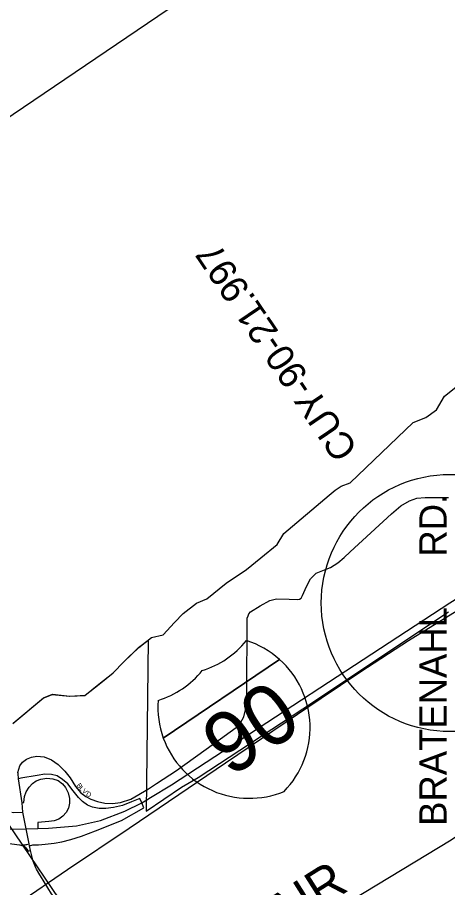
# Model space of a CAD drawing. Extents: x 2139079 to 2262683, y 1235796 to 1334992.
# Drawn here: x 2206334 to 2210756, y 1289914 to 1298857 of the extents above; entities that cross this region are included whole.
import ezdxf

# ---------------------------------------------------------------- set-up
doc = ezdxf.new("R2010")
doc.units = 0
for name, color, linetype in [('Default', 7, 'Continuous'), ('GM_X_City_Street', 7, 'Continuous'), ('GM_X_City_Street_Text', 7, 'Continuous'), ('GM_X_Interchange_Ramps', 7, 'Continuous'), ('GM_X_Interstate_Route', 7, 'Continuous'), ('GM_X_Interstate_Shield', 7, 'Continuous'), ('GM_X_Major_Lake', 7, 'Continuous'), ('GM_X_Rail_Line', 7, 'Continuous'), ('GM_X_US_Route', 7, 'Continuous'), ('SH_Text', 7, 'Continuous')]:
    doc.layers.add(name, color=color, linetype=linetype)

msp = doc.modelspace()

# ---------------------------------------------------------------- linework, layer by layer
at = {"layer": 'GM_X_City_Street'}
for points in [[(2207681, 1290929.7), (2207712.2, 1290948), (2207764.3, 1290982.2), (2207968.5, 1291116.2), (2208359.1, 1291397.6), (2208582.1, 1291558.9), (2208626.3, 1291606.2), (2208661.3, 1291667.1), (2208688.8, 1291783), (2208690.3, 1291929.4), (2208694.1, 1292655.8), (2208696.7, 1292682), (2208704, 1292708), (2208714.1, 1292728.4), (2208729.9, 1292747.6), (2208827.8, 1292810), (2208929, 1292864.9), (2208995.5, 1292881), (2209128.3, 1292879.4), (2209208.4, 1292875.5), (2209233.5, 1292879.4), (2209249.9, 1292886.6), (2209263.4, 1292917), (2209305.9, 1293006.8), (2209345.4, 1293085.9), (2209405.2, 1293145.7), (2209489.7, 1293178.4), (2209552, 1293202.3), (2209628.9, 1293250.3), (2209692.4, 1293305.9), (2209753.9, 1293365.6), (2210179.9, 1293754.7), (2210275.8, 1293835.9), (2210363.2, 1293888.6), (2210439, 1293915), (2210524.9, 1293923.8), (2210765.7, 1293921.8)], [(2206637.8, 1287887.1), (2206870.7, 1288028.3), (2207250.4, 1288258.5), (2210791.9, 1290405.9), (2211061.9, 1290587.5), (2211375.2, 1290789.8), (2211429.3, 1290818.3), (2211504.8, 1290848.2), (2211604.5, 1290868.2), (2211952.5, 1290931.9), (2212611.7, 1291058.6), (2213914.1, 1291343.2), (2214033.3, 1291373.4), (2214154, 1291387), (2214425, 1291386.3)], [(2206340.6, 1291086.3), (2206339.6, 1291096.1), (2206358.4, 1291163.3), (2206386.6, 1291202.2), (2206426.9, 1291233.1), (2206478.4, 1291253.6), (2206534.8, 1291263.5), (2206607.9, 1291256.6), (2206683.3, 1291226.8), (2206752, 1291180.4), (2206822.1, 1291111.8), (2206877.2, 1291041.1), (2206932, 1290953.4), (2206986.9, 1290888.6), (2207035.7, 1290850.5), (2207088.3, 1290822.3), (2207156.8, 1290797.9), (2207233.1, 1290781.1), (2207312.3, 1290779.6), (2207392.3, 1290788), (2207498.9, 1290822.9), (2207681, 1290929.7)], [(2206276.6, 1290687.7), (2206298.3, 1290687), (2206390.7, 1290690), (2206381.6, 1290785.7), (2206346.1, 1291033.1), (2206340.6, 1291086.3)], [(2206455.1, 1290363.6), (2206424.2, 1290518.9), (2206390.7, 1290690)], [(2206524.5, 1290115.7), (2206497.5, 1290183.6), (2206469.8, 1290294.1), (2206459.4, 1290342.2), (2206455.1, 1290363.6)], [(2206572.2, 1290035.5), (2206565.6, 1290046.4), (2206529.4, 1290103.4), (2206524.5, 1290115.7)], [(2206870.7, 1288028.3), (2206801.9, 1288131.6), (2206763, 1288225.5), (2206736.2, 1288313.5), (2206725.6, 1288381.6), (2206736.6, 1288498), (2206777, 1288676.9), (2206816.2, 1288773.5), (2206865, 1288938.8), (2206886.9, 1289050.4), (2206900.2, 1289207.1), (2206899.1, 1289367.4), (2206876.7, 1289479), (2206838.2, 1289622.3), (2206788, 1289727), (2206684.4, 1289851), (2206572.2, 1290035.5)]]:
    msp.add_lwpolyline(points, dxfattribs=at)
at = {"layer": 'GM_X_Interchange_Ramps'}
for points in [[(2207611.2, 1290784.2), (2207591.3, 1290829.6), (2207506.3, 1290794.2), (2207412.4, 1290758.5), (2207323.1, 1290736), (2207241.2, 1290726.5), (2207174, 1290727.1), (2207106.9, 1290739.5), (2207053, 1290761.9), (2207002.2, 1290798.9), (2206960.3, 1290838.8), (2206908.3, 1290908), (2206850.5, 1290981.6), (2206796.9, 1291026), (2206741.7, 1291061.6), (2206683.4, 1291075.3), (2206614.7, 1291078.8), (2206537.2, 1291066.4), (2206370.4, 1291037.3), (2206346.1, 1291033.1)], [(2206381.6, 1290785.7), (2206398.7, 1290788.5), (2206406.6, 1290851.3), (2206424.6, 1290897.9), (2206454.2, 1290944.4), (2206488.2, 1290982.1), (2206526.4, 1291009.5), (2206573.4, 1291029.5), (2206634.8, 1291037.7), (2206697.6, 1291031.3), (2206751.5, 1291013.2), (2206796.4, 1290979.2), (2206826.8, 1290940.9), (2206855.5, 1290886.6), (2206869.6, 1290830.9), (2206870.6, 1290781.2), (2206858.4, 1290728.7), (2206836, 1290685), (2206802.1, 1290648.8), (2206758, 1290617.1), (2206711.1, 1290601.4), (2206656.9, 1290591.7), (2206542.8, 1290581.1), (2206544.6, 1290521)], [(2206459.4, 1290342.2), (2206493.3, 1290351.7), (2206551, 1290353.2), (2206618.8, 1290358.5), (2206711.1, 1290370.5), (2206789.4, 1290382.9), (2206881.6, 1290406.9), (2206993, 1290440.9), (2207135.3, 1290496.6), (2207405.1, 1290603.7), (2207633.2, 1290734), (2207611.2, 1290784.2)], [(2205560.4, 1290495), (2205562.5, 1290436.8), (2205710, 1290425.2), (2205959.7, 1290405.3), (2206353.7, 1290353.4), (2206357.9, 1290352.3), (2206389.2, 1290344.4), (2206402.7, 1290338.7), (2206413.8, 1290329.5), (2206430.7, 1290309), (2206443.1, 1290286.6), (2206469.8, 1290294.1)], [(2206389.2, 1290344.4), (2206391.7, 1290354.5), (2206405.6, 1290353.9), (2206415, 1290353.9), (2206423.1, 1290355.1), (2206431.1, 1290356.8), (2206455.1, 1290363.6)]]:
    msp.add_lwpolyline(points, dxfattribs=at)
at = {"layer": 'GM_X_Interstate_Route'}
for points in [[(2207701.2, 1290838), (2207916.4, 1290971.4), (2210778.7, 1292838.5), (2212470.3, 1293891), (2213134.5, 1294323.1), (2213343.6, 1294459.2), (2214118.6, 1294963.4), (2214122.3, 1294965.7)], [(2206285.4, 1291601.4), (2206599, 1291861.5), (2206690.9, 1291898.4), (2206869.5, 1291879.9), (2207025.8, 1291887.2), (2207169.1, 1292002.9), (2207314.5, 1292116.5), (2207427.8, 1292233.9), (2207579, 1292379.7), (2207676.9, 1292456.5), (2207656.2, 1290700.4), (2208021.4, 1290947.2), (2208191.1, 1291044.4), (2209268.7, 1291750.6), (2210765.4, 1292746)], [(2206424.2, 1290518.9), (2206544.6, 1290521), (2206653.2, 1290522.9), (2206940, 1290548.3), (2207187.7, 1290602.3), (2207437.4, 1290698.2), (2207611.2, 1290784.2), (2207664.5, 1290815.3), (2207701.2, 1290838)], [(2205835.1, 1290506), (2206424.2, 1290518.9)]]:
    msp.add_lwpolyline(points, dxfattribs=at)
at = {"layer": 'GM_X_Interstate_Shield'}
for p, q in [((2207833.7, 1291449.2), (2209028.2, 1292258.3)), ((2209028.2, 1292258.3), (2207833.7, 1291449.2)), ((2209028.2, 1292258.3), (2207833.7, 1291449.2))]:
    msp.add_line(p, q, dxfattribs=at)
for centre, start, end in [((2207957.8, 1293040.8), 287.12046, 321.10231), ((2208404.6, 1291558.3), 48.30474, 72.44243), ((2208404.6, 1291558.3), 315.64835, 48.30474), ((2207504.2, 1292733.6), 287.12046, 321.10231), ((2208715.1, 1291768.6), 175.78035, 199.91803), ((2208715.1, 1291768.6), 199.91803, 292.57443)]:
    msp.add_arc(centre, 937.5, start, end, dxfattribs=at)
at = {"layer": 'GM_X_Major_Lake'}
for points in [[(2208175, 1292835), (2208282.1, 1292880.5), (2208479, 1293041.1), (2208688.2, 1293183.9), (2208835.5, 1293301.9), (2209002.6, 1293438.2), (2209073.6, 1293553.3), (2209537, 1293945.7), (2209598.7, 1293996.6), (2209662.4, 1294039.4), (2209754.4, 1294072.5), (2210402, 1294693.7), (2210531.9, 1294745.3), (2210641.4, 1294822.8), (2210722.2, 1294964.2), (2210891.3, 1295098.5)], [(2206289.8, 1291604), (2206603.4, 1291864.1), (2206695.3, 1291901), (2206873.9, 1291882.5), (2207030.2, 1291889.8), (2207173.5, 1292005.5), (2207318.9, 1292119.1), (2207432.2, 1292236.5), (2207583.4, 1292382.3), (2207712.8, 1292483.8), (2207832.9, 1292510.9), (2207950.1, 1292636.4), (2208037.5, 1292731.5), (2208175, 1292835)]]:
    msp.add_lwpolyline(points, dxfattribs=at)
at = {"layer": 'GM_X_Rail_Line'}
msp.add_lwpolyline([(2203228.1, 1287651), (2204195.4, 1288303.3), (2204797, 1288709.8), (2205631.8, 1289275), (2206337, 1289750.9), (2206850, 1290098.6), (2207481.5, 1290525.3), (2207991.6, 1290871.6), (2208474.1, 1291197), (2209455.6, 1291861.2), (2209862.1, 1292136), (2210353.6, 1292453.2), (2211370.1, 1293079.5), (2212078.2, 1293511.4), (2212986.7, 1294057.2), (2214201.7, 1294795.7), (2216244.5, 1296039.8), (2216686.9, 1296308.3), (2217205.9, 1296624.7), (2218314.7, 1297298.6)], dxfattribs=at)
at = {"layer": 'GM_X_US_Route'}
msp.add_lwpolyline([(2202867.6, 1295541.4), (2210353.6, 1284489.3), (2249318.3, 1310881.6), (2241832.3, 1321933.6)], close=True, dxfattribs=at)
at = {"layer": 'SH_Text'}
msp.add_circle((2210778.7, 1292838.5), 1321, dxfattribs=at)

# ---------------------------------------------------------------- texts
at = {"layer": 'Default'}
msp.add_text('CUY-90-21.997', height=279.999, rotation=124.11128, dxfattribs=at).set_placement((2209842.3, 1294419.3))
at = {"layer": 'GM_X_City_Street_Text'}
for s, height, rotation, p in [('B', 50, 308.20088, (2206938.4, 1290963)), ('L', 50, 311.82254, (2206965.1, 1290929.3)), ('V', 50, 319.43942, (2206993.6, 1290898.1)), ('D', 50, 328.32395, (2207033.8, 1290864.5)), ('ST  CLAIR', 375, 32.23265, (2207725.2, 1288611.6))]:
    msp.add_text(s, height=height, rotation=rotation, dxfattribs=at).set_placement(p)
at = {"layer": 'GM_X_Interchange_Ramps'}
msp.add_text('BRATENAHL     RD.', height=280, rotation=90, dxfattribs=at).set_placement((2210745.3, 1290548.4))
at = {"layer": 'GM_X_Interstate_Shield'}
msp.add_text('90', height=625, rotation=34.11139, dxfattribs=at).set_placement((2208519.5, 1291036.2))

doc.saveas('drawing.dxf')
